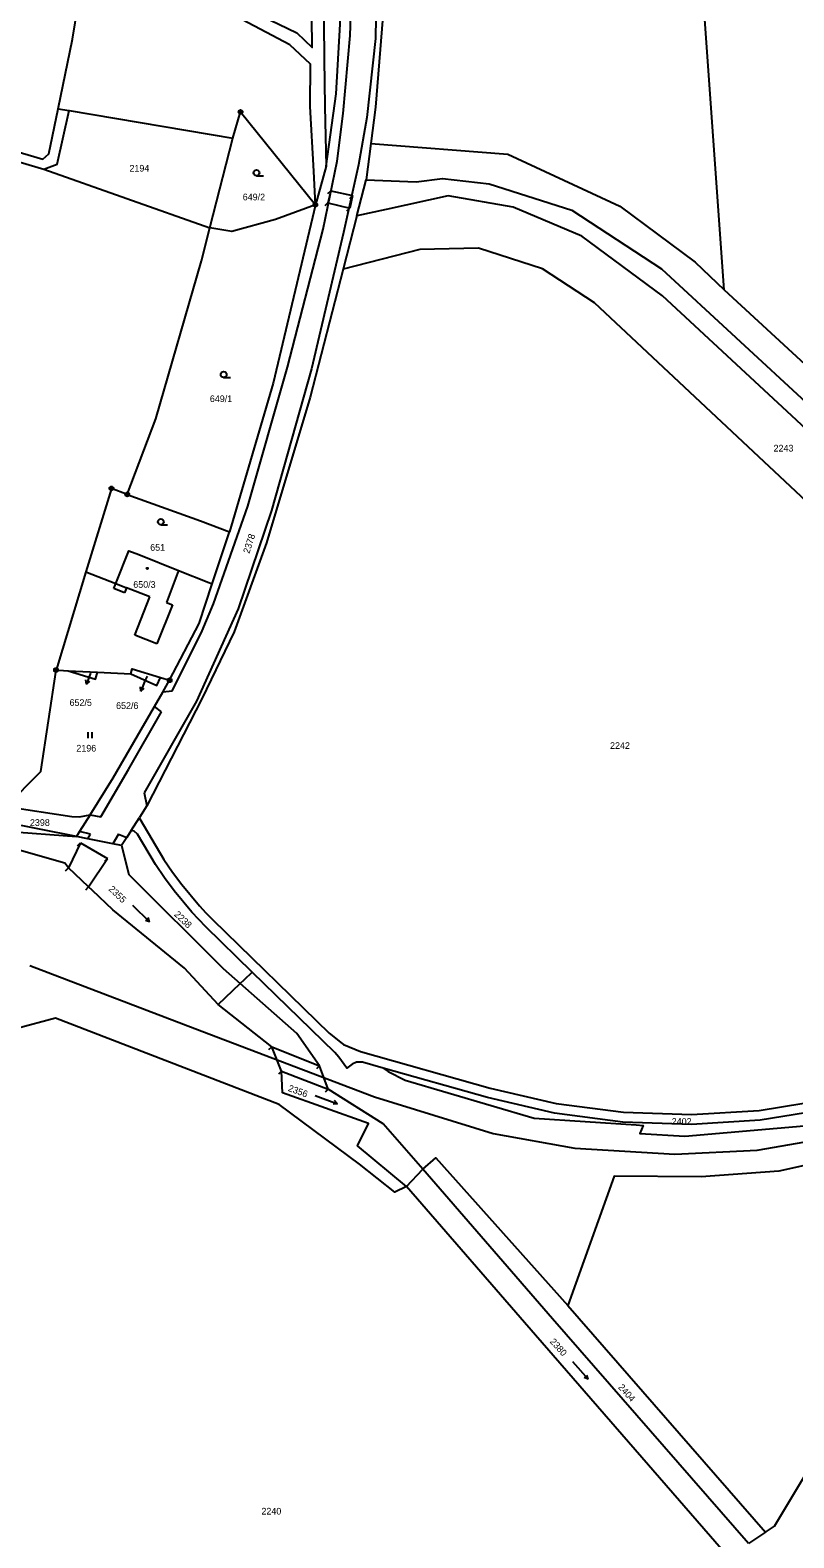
# Model space of a CAD drawing. Extents: x -504988 to -494607, y -1123820 to -1114018.
# Drawn here: x -499234.7 to -499040.2, y -1121962.3 to -1121578.3 of the extents above; entities that cross this region are included whole.
import ezdxf

# ---------------------------------------------------------------- set-up
doc = ezdxf.new("R2010")
doc.units = 0
for name, color, linetype in [('Hranice parcel', 7, 'Continuous'), ('Parcelní čísla', 7, 'Continuous'), ('Pop  PČ popisy', 7, 'Continuous'), ('Poz předměty', 7, 'Continuous'), ('Vnitřní kresba', 7, 'Continuous'), ('Značky bodu BP', 7, 'Continuous'), ('Značky budov', 7, 'Continuous'), ('Značky kultur', 7, 'Continuous')]:
    doc.layers.add(name, color=color, linetype=linetype)

msp = doc.modelspace()

# ---------------------------------------------------------------- linework, layer by layer
at = {"layer": 'Hranice parcel'}
for p, q in [((-499058, -1121644.5), (-499070.44, -1121468.78)), ((-499227.56, -1121598.37), (-499224.76, -1121598.84)), ((-499224.76, -1121598.84), (-499183.1, -1121605.87)), ((-499188.91, -1121628.71), (-499183.1, -1121605.87)), ((-499147.9, -1121607.22), (-499149.08, -1121616.48)), ((-499231.17, -1121613.75), (-499188.91, -1121628.71)), ((-499159.26, -1121612.99), (-499162.05, -1121622.8)), ((-499151.52, -1121625.62), (-499149.08, -1121616.48)), ((-499151.52, -1121625.62), (-499155.01, -1121639.17)), ((-499188.31, -1121719.37), (-499183.95, -1121706.09)), ((-499220.45, -1121716.24), (-499228.08, -1121741.28)), ((-499189.16, -1121719.03), (-499188.31, -1121719.37)), ((-499224.95, -1121741.45), (-499217.51, -1121741.84)), ((-499217.51, -1121741.84), (-499209.07, -1121742.28)), ((-499201.51, -1121743.16), (-499199.15, -1121743.89)), ((-499208.94, -1121782.13), (-499206.83, -1121778.8)), ((-499186.81, -1121826.43), (-499181.21, -1121821.09)), ((-499138.88, -1121872.76), (-499134.7, -1121868.37)), ((-499097.79, -1121903.09), (-499047.42, -1121960.83)), ((-499047.42, -1121960.83), (-499051.76, -1121963.68))]:
    msp.add_line(p, q, dxfattribs=at)
for points in [[(-499148.92, -1121482.66), (-499151.99, -1121489.8), (-499152.53, -1121496.5), (-499148.87, -1121517.16), (-499144.44, -1121538.16), (-499143.29, -1121550.17), (-499144.06, -1121564.3), (-499145.09, -1121578.05), (-499146.72, -1121597.96), (-499147.9, -1121607.22)], [(-499162.05, -1121622.8), (-499162.48, -1121614.28), (-499163.33, -1121597.76), (-499163.31, -1121586.97), (-499168.56, -1121582.06), (-499183.66, -1121574.09), (-499202.27, -1121562.18), (-499215.74, -1121551.14), (-499215.43, -1121548.15), (-499200.68, -1121559.65), (-499182.46, -1121571.45), (-499166.75, -1121579.02), (-499162.88, -1121582.74), (-499163.03, -1121567.13), (-499162.78, -1121544.88), (-499161.92, -1121530.92), (-499159.93, -1121519.8)], [(-499158.02, -1121526.21), (-499158.87, -1121531.9), (-499159.59, -1121545), (-499159.98, -1121567.16), (-499159.8, -1121585.73), (-499159.61, -1121597.79), (-499159.26, -1121612.99)], [(-499159.26, -1121612.99), (-499156.71, -1121594.53), (-499155.7, -1121576.86), (-499154.96, -1121552.31), (-499155.68, -1121538.62), (-499158.02, -1121526.21)], [(-499227.56, -1121598.37), (-499223.91, -1121580.64), (-499220.01, -1121556.6), (-499218.85, -1121549.48)], [(-499302.25, -1121591.23), (-499286.96, -1121594.9), (-499268.73, -1121600.24), (-499261.12, -1121602.47), (-499231.44, -1121611.23), (-499229.91, -1121609.8), (-499227.56, -1121598.37)], [(-499302.71, -1121593.93), (-499287.44, -1121597.08), (-499231.17, -1121613.75)], [(-499231.17, -1121613.75), (-499227.81, -1121612.46), (-499224.76, -1121598.84)], [(-499183.1, -1121605.87), (-499181.1, -1121599.15), (-499162.05, -1121622.8)], [(-499147.9, -1121607.22), (-499113.01, -1121609.93), (-499084.54, -1121623.16), (-499065.31, -1121637.39), (-499058, -1121644.5)], [(-499149.08, -1121616.48), (-499136.35, -1121616.98), (-499129.71, -1121616.1), (-499117.81, -1121617.5), (-499096.78, -1121624.2), (-499073.93, -1121639.14), (-499036.06, -1121674.08), (-499003.69, -1121704.58), (-498983.09, -1121724.69), (-498963.04, -1121744.39), (-498933.88, -1121770.18), (-498925.38, -1121778.5)], [(-499162.05, -1121622.8), (-499172.18, -1121626.53), (-499183.28, -1121629.62), (-499188.91, -1121628.71)], [(-499162.05, -1121622.8), (-499172.78, -1121668.24), (-499183.95, -1121706.09)], [(-498929.86, -1121782.17), (-498965.23, -1121747.63), (-498986.15, -1121727.51), (-499007.63, -1121707.59), (-499039.56, -1121677.69), (-499073.7, -1121646), (-499094.22, -1121630.8), (-499111.67, -1121623.38), (-499128.27, -1121620.51), (-499144.04, -1121623.98), (-499151.52, -1121625.62)], [(-499209.94, -1121696.56), (-499202.66, -1121677.32), (-499191.04, -1121637.09), (-499188.91, -1121628.71)], [(-498937.2, -1121791.9), (-499014.09, -1121719.86), (-499090.98, -1121647.81), (-499104.22, -1121639.12), (-499120.52, -1121633.88), (-499135.44, -1121634.17), (-499155.01, -1121639.17)], [(-499155.01, -1121639.17), (-499163.41, -1121671.82), (-499174.51, -1121708.85), (-499182.72, -1121731.59), (-499190.99, -1121748.63), (-499204.95, -1121775.83), (-499206.83, -1121778.8)], [(-499058, -1121644.5), (-499023.32, -1121676.35), (-498990.43, -1121706.85)], [(-499209.94, -1121696.56), (-499213.97, -1121695.03), (-499220.45, -1121716.24)], [(-499209.94, -1121696.56), (-499191.31, -1121703.27), (-499183.95, -1121706.09)], [(-499220.45, -1121716.24), (-499212.85, -1121719.26), (-499209.55, -1121710.93), (-499207.01, -1121711.9), (-499196.86, -1121715.97), (-499189.16, -1121719.03)], [(-499199.15, -1121743.89), (-499191.62, -1121729.45), (-499188.31, -1121719.37)], [(-499240.79, -1121776.06), (-499231.91, -1121767.1), (-499228.08, -1121741.28)], [(-499228.08, -1121741.28), (-499226.2, -1121741.38), (-499224.95, -1121741.45)], [(-499224.95, -1121741.45), (-499218.07, -1121743.59), (-499217.51, -1121741.84)], [(-499209.07, -1121742.28), (-499208.66, -1121740.94), (-499201.51, -1121743.16)], [(-499209.07, -1121742.28), (-499202.37, -1121745.18), (-499201.51, -1121743.16)], [(-499219.4, -1121778.14), (-499213.56, -1121768.77), (-499203.01, -1121750.56), (-499200.89, -1121746.9), (-499199.15, -1121743.89)], [(-499240.79, -1121776.06), (-499224.09, -1121778.56), (-499222.1, -1121778.65), (-499219.4, -1121778.14)], [(-499222.87, -1121783.7), (-499241.68, -1121779.96), (-499245.51, -1121778.94)], [(-499219.4, -1121778.14), (-499222.06, -1121782.4), (-499222.87, -1121783.7)], [(-499206.83, -1121778.8), (-499206.72, -1121779.2), (-499200.59, -1121789.51), (-499198.46, -1121792.79), (-499196.07, -1121795.88), (-499191.54, -1121801.29), (-499189.91, -1121803.14), (-499188.19, -1121804.91), (-499158.57, -1121833.78), (-499155.23, -1121836.37), (-499154.87, -1121836.59), (-499150.59, -1121838.39), (-499117.55, -1121847.75), (-499100.71, -1121851.65), (-499083.57, -1121853.9), (-499066.3, -1121854.49), (-499049.05, -1121853.41), (-499031.98, -1121850.67)], [(-499277.43, -1121782.94), (-499264.28, -1121782.73), (-499240.98, -1121782.27), (-499222.87, -1121783.7)], [(-499211.37, -1121785.96), (-499213.63, -1121785.52), (-499220.02, -1121784.26), (-499222.87, -1121783.7)], [(-499208.94, -1121782.13), (-499210.08, -1121783.92), (-499211.37, -1121785.96)], [(-499178.15, -1121818.18), (-499189.93, -1121806.7), (-499191.74, -1121804.84), (-499193.46, -1121802.9), (-499197.99, -1121797.49), (-499200.5, -1121794.23), (-499202.74, -1121790.79), (-499207.32, -1121783.09), (-499208.17, -1121782.31), (-499208.94, -1121782.13)], [(-498927.99, -1121783.94), (-498932.56, -1121787.75), (-498933.39, -1121788.82), (-498933.98, -1121789.86), (-498934.47, -1121791.14), (-498934.74, -1121792.4), (-498935.36, -1121796.74), (-498936.68, -1121800.66), (-498939.32, -1121803.84), (-498953.28, -1121815.39), (-498967.31, -1121825.9), (-498982.28, -1121835), (-498998.06, -1121842.62), (-499014.51, -1121848.67), (-499031.47, -1121853.11), (-499048.77, -1121855.9), (-499066.26, -1121856.99), (-499083.78, -1121856.4), (-499101.15, -1121854.11), (-499118.23, -1121850.16), (-499144.81, -1121842.63)], [(-499186.81, -1121826.43), (-499195.41, -1121817.18), (-499213.63, -1121802.31), (-499218.83, -1121797.44), (-499219.78, -1121796.5), (-499224.93, -1121791.66), (-499225.82, -1121790.5), (-499241.01, -1121786.13), (-499258.14, -1121786.08), (-499275.4, -1121786.18)], [(-499211.37, -1121785.96), (-499209.51, -1121793.38), (-499185.49, -1121817.31), (-499181.21, -1121821.09)], [(-499144.81, -1121842.63), (-499143.52, -1121843.53), (-499139.17, -1121845.68), (-499106.35, -1121855.43), (-499080.4, -1121857.12), (-499078.61, -1121857.24), (-499079.46, -1121859.32), (-499067.94, -1121859.99), (-499033.65, -1121857.01), (-499012.44, -1121852.99), (-499010.15, -1121850.53), (-498993.59, -1121844.27), (-498973.79, -1121833.82), (-498952.54, -1121819.34), (-498918.2, -1121792.88)], [(-498905.05, -1121806.02), (-498911.48, -1121801.01), (-498950.02, -1121830.34), (-498969.17, -1121842.68), (-499008.55, -1121858.61), (-499009.88, -1121861.29), (-499044.06, -1121868.88), (-499063.78, -1121870.36), (-499085.95, -1121870.14), (-499097.79, -1121903.09)], [(-499047.42, -1121960.83), (-499045.12, -1121959.32), (-499033.21, -1121939.35), (-498987.34, -1121892.56), (-498914.04, -1121816.6), (-498905.05, -1121806.02)], [(-499181.21, -1121821.09), (-499180.11, -1121820.05), (-499178.15, -1121818.18)], [(-499144.81, -1121842.63), (-499150.06, -1121841.14), (-499151.59, -1121841.12), (-499152.64, -1121841.6), (-499154.06, -1121842.64), (-499156.07, -1121839.89), (-499156.57, -1121839.27), (-499157.11, -1121838.69), (-499178.15, -1121818.18)], [(-499134.7, -1121868.37), (-499144.78, -1121856.85), (-499158.79, -1121847.97), (-499160.96, -1121842.06), (-499166.76, -1121833.85), (-499181.21, -1121821.09)], [(-499138.88, -1121872.76), (-499151.29, -1121862.4), (-499148.5, -1121856.73), (-499170.45, -1121848.95), (-499170.65, -1121843.39), (-499173.15, -1121837.22), (-499186.81, -1121826.43)], [(-499138.88, -1121872.76), (-499141.84, -1121874.23), (-499150.81, -1121867.09), (-499171.29, -1121851.94), (-499228.2, -1121829.93), (-499238.28, -1121832.61)], [(-499134.7, -1121868.37), (-499131.34, -1121865.49), (-499097.79, -1121903.09)], [(-499051.76, -1121963.68), (-499101.64, -1121906.47), (-499134.7, -1121868.37)], [(-499056.93, -1121967.07), (-499106, -1121910.64), (-499138.88, -1121872.76)]]:
    msp.add_lwpolyline(points, dxfattribs=at)
at = {"layer": 'Pop  PČ popisy'}
for p, q in [((-499219.3, -1121742.05), (-499220.33, -1121744.87)), ((-499220.33, -1121744.87), (-499220.45, -1121743.76)), ((-499220.33, -1121744.87), (-499219.51, -1121744.1)), ((-499206.52, -1121746.65), (-499206.59, -1121745.53)), ((-499205.35, -1121743.89), (-499206.52, -1121746.65)), ((-499206.52, -1121746.65), (-499205.67, -1121745.93)), ((-499204.89, -1121742.82), (-499205.35, -1121743.89))]:
    msp.add_line(p, q, dxfattribs=at)
at = {"layer": 'Poz předměty'}
for p, q in [((-499234.72, -1121816.5), (-499190.96, -1121833.21)), ((-499190.96, -1121833.21), (-499146.98, -1121849.94)), ((-499146.98, -1121849.94), (-499116.75, -1121859.26)), ((-499116.75, -1121859.26), (-499096.02, -1121863.01)), ((-499049.55, -1121863.51), (-499023.19, -1121858.99)), ((-499096.02, -1121863.01), (-499070.54, -1121864.59)), ((-499070.54, -1121864.59), (-499049.55, -1121863.51))]:
    msp.add_line(p, q, dxfattribs=at)
at = {"layer": 'Vnitřní kresba'}
for p, q in [((-499153.22, -1121579.74), (-499152.27, -1121555.68)), ((-499146.31, -1121556.52), (-499146.74, -1121580.5)), ((-499154.97, -1121599.59), (-499153.22, -1121579.74)), ((-499146.74, -1121580.5), (-499148.95, -1121600.58)), ((-499156.5, -1121611.69), (-499154.97, -1121599.59)), ((-499148.95, -1121600.58), (-499151.08, -1121612.61)), ((-499160.09, -1121628.99), (-499156.5, -1121611.69)), ((-499151.08, -1121612.61), (-499154.88, -1121629.91)), ((-499158.13, -1121619.24), (-499158.86, -1121622.32)), ((-499158.84, -1121619.95), (-499158.13, -1121619.24)), ((-499158.13, -1121619.24), (-499152.56, -1121620.49)), ((-499159.57, -1121623.03), (-499158.86, -1121622.32)), ((-499158.86, -1121622.32), (-499153.31, -1121623.67)), ((-499154.02, -1121624.38), (-499153.31, -1121623.67)), ((-499152.56, -1121620.49), (-499153.31, -1121623.67)), ((-499153.27, -1121621.2), (-499152.56, -1121620.49)), ((-499169.13, -1121664.12), (-499160.09, -1121628.99)), ((-499154.88, -1121629.91), (-499163, -1121664.58)), ((-499179.26, -1121699.54), (-499169.13, -1121664.12)), ((-499163, -1121664.58), (-499173.24, -1121700.62)), ((-499187.97, -1121724.41), (-499179.26, -1121699.54)), ((-499173.24, -1121700.62), (-499181.69, -1121725.67)), ((-499213.34, -1121720.49), (-499212.85, -1121719.26)), ((-499212.85, -1121719.26), (-499210.12, -1121720.34)), ((-499196.86, -1121715.97), (-499199.91, -1121724.1)), ((-499210.61, -1121721.58), (-499213.34, -1121720.49)), ((-499210.12, -1121720.34), (-499210.61, -1121721.58)), ((-499204.23, -1121722.68), (-499210.12, -1121720.34)), ((-499208.04, -1121732.41), (-499204.23, -1121722.68)), ((-499198.45, -1121724.71), (-499202.4, -1121734.61)), ((-499199.91, -1121724.1), (-499198.45, -1121724.71)), ((-499181.69, -1121725.67), (-499192.33, -1121749.2)), ((-499190.83, -1121731.3), (-499187.97, -1121724.41)), ((-499202.4, -1121734.61), (-499208.04, -1121732.41)), ((-499198.53, -1121746.64), (-499190.83, -1121731.3)), ((-499192.33, -1121749.2), (-499205.6, -1121772.55)), ((-499198.53, -1121746.64), (-499200.89, -1121746.9)), ((-499209.66, -1121766.64), (-499201.24, -1121751.9)), ((-499201.24, -1121751.9), (-499203.01, -1121750.56)), ((-499216.71, -1121778.69), (-499209.66, -1121766.64)), ((-499205.6, -1121772.55), (-499204.95, -1121775.83)), ((-499219.4, -1121778.14), (-499216.71, -1121778.69)), ((-499219.3, -1121783.04), (-499222.06, -1121782.4)), ((-499220.02, -1121784.26), (-499219.3, -1121783.04)), ((-499212.19, -1121783.08), (-499213.63, -1121785.52)), ((-499212.19, -1121783.08), (-499210.08, -1121783.92)), ((-499221.86, -1121785.3), (-499224.93, -1121791.66)), ((-499222.57, -1121786.01), (-499221.86, -1121785.3)), ((-499221.86, -1121785.3), (-499214.96, -1121789.26)), ((-499225.64, -1121792.37), (-499224.93, -1121791.66)), ((-499219.78, -1121796.5), (-499214.96, -1121789.26)), ((-499215.67, -1121789.97), (-499214.96, -1121789.26)), ((-499220.49, -1121797.21), (-499219.78, -1121796.5)), ((-499173.86, -1121837.93), (-499173.15, -1121837.22)), ((-499173.15, -1121837.22), (-499160.96, -1121842.06)), ((-499161.67, -1121842.77), (-499160.96, -1121842.06)), ((-499171.36, -1121844.1), (-499170.65, -1121843.39)), ((-499170.65, -1121843.39), (-499158.79, -1121847.97)), ((-499159.5, -1121848.68), (-499158.79, -1121847.97))]:
    msp.add_line(p, q, dxfattribs=at)
at = {"layer": 'Značky bodu BP'}
for centre, radius in [((-499181.1, -1121599.15), 0.5), ((-499181.1, -1121599.15), 0.0303), ((-499162.05, -1121622.8), 0.5), ((-499162.05, -1121622.8), 0.0303), ((-499213.97, -1121695.03), 0.5), ((-499213.97, -1121695.03), 0.0303), ((-499209.94, -1121696.56), 0.5), ((-499209.94, -1121696.56), 0.0303), ((-499228.08, -1121741.28), 0.5), ((-499228.08, -1121741.28), 0.0303), ((-499199.15, -1121743.89), 0.5), ((-499199.15, -1121743.89), 0.0303)]:
    msp.add_circle(centre, radius, dxfattribs=at)
at = {"layer": 'Značky budov'}
msp.add_circle((-499204.86, -1121715.4), 0.175, dxfattribs=at)
at = {"layer": 'Značky kultur'}
for p, q in [((-499177.03, -1121615.43), (-499175.28, -1121615.43)), ((-499185.4, -1121666.8), (-499183.65, -1121666.8)), ((-499201.41, -1121704.29), (-499199.66, -1121704.29)), ((-499219.91, -1121758.62), (-499219.91, -1121757.12)), ((-499218.91, -1121758.62), (-499218.91, -1121757.12)), ((-499208.57, -1121801.19), (-499204.26, -1121805.36)), ((-499204.26, -1121805.36), (-499205.31, -1121805.04)), ((-499204.26, -1121805.36), (-499204.61, -1121804.32)), ((-499162.07, -1121849.65), (-499156.43, -1121851.7)), ((-499156.43, -1121851.7), (-499157.52, -1121851.84)), ((-499156.43, -1121851.7), (-499157.17, -1121850.9)), ((-499096.62, -1121917.39), (-499092.61, -1121921.85)), ((-499092.61, -1121921.85), (-499093.63, -1121921.46)), ((-499092.61, -1121921.85), (-499092.89, -1121920.79))]:
    msp.add_line(p, q, dxfattribs=at)
for centre in [(-499177.03, -1121614.68), (-499185.4, -1121666.05), (-499201.41, -1121703.54)]:
    msp.add_circle(centre, 0.75, dxfattribs=at)

# ---------------------------------------------------------------- texts
at = {"layer": 'Parcelní čísla'}
for s, p in [('2194', (-499209.38, -1121614.36)), ('649/2', (-499180.54, -1121621.68)), ('649/1', (-499188.91, -1121673.05)), ('2243', (-499045.39, -1121685.64)), ('651', (-499204.1, -1121710.91)), ('650/3', (-499208.41, -1121720.35)), ('652/5', (-499224.64, -1121750.42)), ('652/6', (-499212.78, -1121751.19)), ('2196', (-499222.9, -1121762.04)), ('2242', (-499087.02, -1121761.36)), ('2398', (-499234.72, -1121780.97)), ('2402', (-499071.31, -1121857.08)), ('2240', (-499175.78, -1121956.32))]:
    msp.add_text(s, height=1.7, dxfattribs=at).set_placement(p)
for s, rotation, p in [('2378', 72, (-499178.88, -1121711.74)), ('2355', 316, (-499214.82, -1121797.24)), ('2238', 316, (-499198.13, -1121803.67)), ('2356', 340, (-499169.13, -1121848.42)), ('2380', 312, (-499102.47, -1121912.39)), ('2404', 312, (-499085.07, -1121924.02))]:
    msp.add_text(s, height=1.7, rotation=rotation, dxfattribs=at).set_placement(p)

doc.saveas('drawing.dxf')
